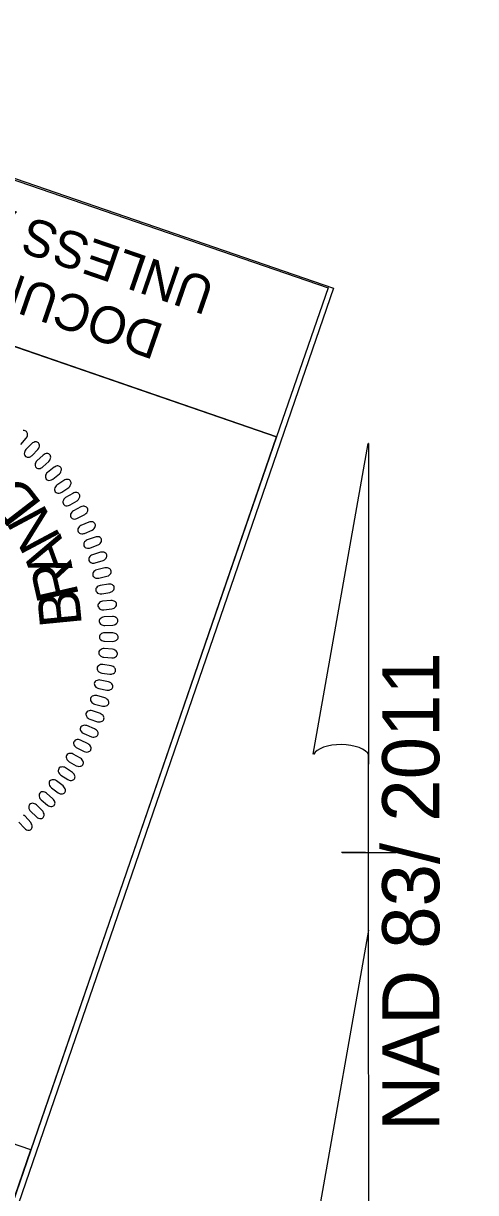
# Model space of a CAD drawing. Extents: x 479650 to 481768, y 492454 to 494037.
# Drawn here: x 479874 to 479941.4, y 492981.7 to 493156.1 of the extents above; entities that cross this region are included whole.
import ezdxf

# ---------------------------------------------------------------- set-up
doc = ezdxf.new("R2010")
doc.units = 0
for name, color, linetype in [('Prop North Arrow NAD83 for Plan Sheets CELL', 7, 'Continuous'), ('Sheet Clip Boundary CELL', 7, 'Continuous'), ('Sheet PE Seal Cell', 7, 'Continuous'), ('Sheet Plan CELL', 7, 'Continuous'), ('Sheet Sticker Exception Certification CELL', 7, 'Continuous')]:
    doc.layers.add(name, color=color, linetype=linetype)

msp = doc.modelspace()

# ---------------------------------------------------------------- linework, layer by layer
at = {"layer": 'Prop North Arrow NAD83 for Plan Sheets CELL'}
for p, q in [((479917.21, 493047.06), (479925.41, 493093.41)), ((479925.46, 493093.41), (479925.41, 493093.41)), ((479925.46, 493093.41), (479925.41, 493093.41)), ((479925.46, 493093.41), (479925.46, 493045.61)), ((479925.46, 493020.81), (479925.46, 493047.01)), ((479925.46, 493045.61), (479925.46, 493046.96)), ((479921.46, 493032.41), (479921.41, 493032.41)), ((479925.01, 493032.41), (479921.46, 493032.41)), ((479921.51, 493032.41), (479929.51, 493032.41)), ((479925.46, 493020.81), (479917.11, 492973.56)), ((479925.51, 492973.76), (479925.46, 493020.81))]:
    msp.add_line(p, q, dxfattribs=at)
msp.add_ellipse((479921.35, 493046.56), major_axis=(4.23, -0.03), ratio=0.461098, start_param=0.216388, end_param=2.908219, dxfattribs=at)
at = {"layer": 'Sheet Clip Boundary CELL'}
msp.add_lwpolyline([(480865.41, 492806.9), (480865.41, 492806.9), (481216.52, 493064.43), (481296.64, 493123.2), (481433.97, 493521.82), (480177.88, 493954.83), (480146.86, 493864.82), (480073.72, 493890.25), (479959.68, 493732.81), (479819.95, 493331.12), (479813.6, 493153.33), (479920.24, 493116.59), (479863.72, 492952.49), (480677.4, 492672.07), (480745.44, 492725.05)], close=True, dxfattribs=at)
at = {"layer": 'Sheet PE Seal Cell'}
for points in [[(479873.62, 493093.28), (479874.42, 493094.22), (479874.54, 493094.41), (479874.59, 493094.55), (479874.61, 493094.75), (479874.61, 493094.89), (479874.58, 493095.03), (479874.53, 493095.13), (479874.45, 493095.21), (479874.36, 493095.27), (479874.24, 493095.33), (479874.13, 493095.35), (479873.98, 493095.34)], [(479873.32, 493036.93), (479874.15, 493036.02), (479874.32, 493035.88), (479874.45, 493035.81), (479874.65, 493035.76), (479874.8, 493035.75), (479874.93, 493035.76), (479875.04, 493035.8), (479875.13, 493035.86), (479875.2, 493035.95), (479875.27, 493036.06), (479875.31, 493036.17), (479875.32, 493036.31), (479875.31, 493036.41), (479875.26, 493036.57), (479875.18, 493036.74), (479875.09, 493036.88), (479874.26, 493037.81), (479874.13, 493037.92), (479874, 493038)]]:
    msp.add_lwpolyline(points, dxfattribs=at)
for points in [[(479875.31, 493091.64), (479876.16, 493092.52), (479876.29, 493092.7), (479876.35, 493092.84), (479876.39, 493093.04), (479876.39, 493093.18), (479876.37, 493093.32), (479876.32, 493093.42), (479876.26, 493093.51), (479876.16, 493093.58), (479876.06, 493093.64), (479875.94, 493093.67), (479875.79, 493093.67), (479875.69, 493093.65), (479875.54, 493093.59), (479875.37, 493093.51), (479875.25, 493093.41), (479874.37, 493092.51), (479874.26, 493092.38), (479874.2, 493092.24), (479874.15, 493092.07), (479874.13, 493091.89), (479874.15, 493091.76), (479874.22, 493091.61), (479874.31, 493091.49), (479874.45, 493091.42), (479874.56, 493091.38), (479874.72, 493091.36), (479874.92, 493091.4), (479875.09, 493091.48), (479875.21, 493091.56)], [(479876.89, 493089.92), (479877.8, 493090.74), (479877.94, 493090.92), (479878.01, 493091.05), (479878.06, 493091.25), (479878.08, 493091.39), (479878.06, 493091.53), (479878.02, 493091.64), (479877.96, 493091.73), (479877.87, 493091.8), (479877.77, 493091.87), (479877.65, 493091.91), (479877.51, 493091.92), (479877.41, 493091.91), (479877.25, 493091.86), (479877.08, 493091.78), (479876.95, 493091.69), (479876.01, 493090.85), (479875.9, 493090.72), (479875.83, 493090.6), (479875.77, 493090.42), (479875.74, 493090.25), (479875.74, 493090.12), (479875.81, 493089.96), (479875.89, 493089.84), (479876.02, 493089.76), (479876.13, 493089.71), (479876.29, 493089.68), (479876.49, 493089.71), (479876.67, 493089.78), (479876.79, 493089.84)], [(479878.41, 493088.11), (479879.37, 493088.88), (479879.51, 493089.05), (479879.59, 493089.17), (479879.65, 493089.37), (479879.68, 493089.51), (479879.67, 493089.65), (479879.64, 493089.76), (479879.58, 493089.86), (479879.5, 493089.93), (479879.4, 493090.01), (479879.29, 493090.05), (479879.14, 493090.07), (479879.04, 493090.07), (479878.88, 493090.03), (479878.71, 493089.96), (479878.57, 493089.88), (479877.58, 493089.1), (479877.46, 493088.98), (479877.38, 493088.86), (479877.31, 493088.69), (479877.27, 493088.51), (479877.27, 493088.39), (479877.32, 493088.23), (479877.4, 493088.1), (479877.53, 493088), (479877.63, 493087.95), (479877.79, 493087.92), (479877.99, 493087.93), (479878.18, 493087.99), (479878.3, 493088.05)], [(479879.74, 493086.16), (479880.75, 493086.86), (479880.91, 493087.02), (479880.99, 493087.14), (479881.07, 493087.33), (479881.1, 493087.47), (479881.1, 493087.61), (479881.07, 493087.72), (479881.03, 493087.82), (479880.95, 493087.9), (479880.85, 493087.98), (479880.74, 493088.04), (479880.6, 493088.06), (479880.5, 493088.07), (479880.34, 493088.04), (479880.16, 493087.98), (479880.02, 493087.91), (479878.98, 493087.2), (479878.86, 493087.08), (479878.77, 493086.96), (479878.69, 493086.8), (479878.64, 493086.63), (479878.63, 493086.5), (479878.67, 493086.34), (479878.74, 493086.2), (479878.86, 493086.1), (479878.96, 493086.05), (479879.11, 493086), (479879.32, 493086), (479879.51, 493086.05), (479879.63, 493086.1)], [(479880.97, 493084.25), (479882.02, 493084.89), (479882.19, 493085.04), (479882.28, 493085.16), (479882.37, 493085.34), (479882.41, 493085.48), (479882.42, 493085.62), (479882.4, 493085.73), (479882.36, 493085.83), (479882.28, 493085.92), (479882.19, 493086.01), (479882.09, 493086.06), (479881.95, 493086.1), (479881.85, 493086.11), (479881.69, 493086.09), (479881.5, 493086.05), (479881.35, 493085.98), (479880.28, 493085.34), (479880.14, 493085.23), (479880.05, 493085.12), (479879.96, 493084.96), (479879.9, 493084.79), (479879.88, 493084.67), (479879.91, 493084.5), (479879.97, 493084.36), (479880.08, 493084.26), (479880.18, 493084.19), (479880.33, 493084.14), (479880.54, 493084.12), (479880.73, 493084.16), (479880.85, 493084.2)], [(479882.07, 493082.26), (479883.16, 493082.83), (479883.33, 493082.96), (479883.43, 493083.08), (479883.53, 493083.25), (479883.58, 493083.39), (479883.6, 493083.53), (479883.59, 493083.64), (479883.55, 493083.75), (479883.48, 493083.84), (479883.4, 493083.93), (479883.3, 493083.99), (479883.16, 493084.04), (479883.06, 493084.06), (479882.9, 493084.05), (479882.71, 493084.01), (479882.56, 493083.96), (479881.45, 493083.38), (479881.31, 493083.28), (479881.2, 493083.18), (479881.1, 493083.02), (479881.03, 493082.86), (479881.01, 493082.74), (479881.03, 493082.57), (479881.08, 493082.43), (479881.18, 493082.31), (479881.28, 493082.25), (479881.42, 493082.18), (479881.63, 493082.15), (479881.82, 493082.18), (479881.95, 493082.21)], [(479883.13, 493080.01), (479884.25, 493080.51), (479884.44, 493080.64), (479884.54, 493080.74), (479884.65, 493080.91), (479884.71, 493081.05), (479884.74, 493081.18), (479884.73, 493081.29), (479884.7, 493081.4), (479884.64, 493081.5), (479884.56, 493081.6), (479884.47, 493081.67), (479884.33, 493081.72), (479884.24, 493081.74), (479884.07, 493081.74), (479883.88, 493081.72), (479883.73, 493081.68), (479882.58, 493081.17), (479882.43, 493081.08), (479882.32, 493080.98), (479882.22, 493080.84), (479882.13, 493080.68), (479882.1, 493080.56), (479882.11, 493080.39), (479882.15, 493080.24), (479882.25, 493080.12), (479882.34, 493080.05), (479882.48, 493079.97), (479882.69, 493079.93), (479882.88, 493079.95), (479883.01, 493079.97)], [(479883.98, 493077.85), (479885.13, 493078.28), (479885.32, 493078.39), (479885.44, 493078.49), (479885.56, 493078.65), (479885.62, 493078.78), (479885.66, 493078.91), (479885.66, 493079.02), (479885.64, 493079.14), (479885.58, 493079.23), (479885.51, 493079.34), (479885.42, 493079.41), (479885.29, 493079.48), (479885.19, 493079.5), (479885.03, 493079.51), (479884.84, 493079.51), (479884.68, 493079.47), (479883.5, 493079.04), (479883.35, 493078.96), (479883.24, 493078.87), (479883.12, 493078.73), (479883.03, 493078.57), (479882.99, 493078.45), (479882.99, 493078.29), (479883.02, 493078.14), (479883.11, 493078.01), (479883.19, 493077.93), (479883.33, 493077.85), (479883.53, 493077.8), (479883.73, 493077.8), (479883.86, 493077.81)], [(479884.7, 493075.61), (479885.87, 493075.97), (479886.07, 493076.07), (479886.19, 493076.16), (479886.32, 493076.31), (479886.39, 493076.44), (479886.44, 493076.57), (479886.45, 493076.68), (479886.43, 493076.8), (479886.38, 493076.9), (479886.32, 493077), (479886.23, 493077.08), (479886.1, 493077.16), (479886.01, 493077.19), (479885.85, 493077.21), (479885.66, 493077.21), (479885.5, 493077.19), (479884.29, 493076.83), (479884.14, 493076.76), (479884.02, 493076.67), (479883.89, 493076.54), (479883.79, 493076.4), (479883.74, 493076.28), (479883.73, 493076.11), (479883.76, 493075.96), (479883.84, 493075.83), (479883.92, 493075.75), (479884.05, 493075.65), (479884.24, 493075.59), (479884.44, 493075.58), (479884.57, 493075.59)], [(479885.26, 493073.33), (479886.45, 493073.61), (479886.66, 493073.7), (479886.78, 493073.78), (479886.92, 493073.93), (479887.01, 493074.05), (479887.06, 493074.18), (479887.07, 493074.29), (479887.07, 493074.4), (479887.02, 493074.5), (479886.96, 493074.61), (479886.88, 493074.7), (479886.76, 493074.78), (479886.67, 493074.82), (479886.51, 493074.85), (479886.32, 493074.87), (479886.16, 493074.85), (479884.93, 493074.57), (479884.77, 493074.51), (479884.65, 493074.43), (479884.52, 493074.31), (479884.4, 493074.17), (479884.35, 493074.05), (479884.33, 493073.89), (479884.34, 493073.74), (479884.42, 493073.6), (479884.49, 493073.51), (479884.62, 493073.41), (479884.81, 493073.33), (479885, 493073.31), (479885.13, 493073.31)], [(479885.68, 493070.99), (479886.89, 493071.2), (479887.1, 493071.27), (479887.23, 493071.35), (479887.37, 493071.48), (479887.47, 493071.6), (479887.52, 493071.72), (479887.55, 493071.83), (479887.55, 493071.95), (479887.51, 493072.05), (479887.46, 493072.17), (479887.38, 493072.26), (479887.27, 493072.35), (479887.18, 493072.39), (479887.02, 493072.43), (479886.83, 493072.46), (479886.67, 493072.46), (479885.43, 493072.25), (479885.27, 493072.2), (479885.14, 493072.13), (479885, 493072.02), (479884.88, 493071.88), (479884.81, 493071.77), (479884.78, 493071.61), (479884.79, 493071.46), (479884.85, 493071.32), (479884.92, 493071.22), (479885.04, 493071.11), (479885.23, 493071.02), (479885.42, 493070.99), (479885.55, 493070.98)], [(479885.97, 493068.61), (479887.19, 493068.75), (479887.4, 493068.81), (479887.54, 493068.87), (479887.69, 493069), (479887.79, 493069.11), (479887.86, 493069.23), (479887.89, 493069.34), (479887.89, 493069.45), (479887.86, 493069.56), (479887.82, 493069.68), (479887.75, 493069.78), (479887.64, 493069.87), (479887.55, 493069.92), (479887.4, 493069.97), (479887.21, 493070.01), (479887.05, 493070.02), (479885.8, 493069.89), (479885.63, 493069.85), (479885.5, 493069.79), (479885.35, 493069.68), (479885.22, 493069.56), (479885.16, 493069.45), (479885.11, 493069.29), (479885.11, 493069.14), (479885.17, 493068.99), (479885.23, 493068.9), (479885.34, 493068.78), (479885.52, 493068.68), (479885.71, 493068.63), (479885.84, 493068.62)], [(479886.12, 493066.28), (479887.34, 493066.34), (479887.56, 493066.38), (479887.7, 493066.44), (479887.86, 493066.56), (479887.97, 493066.66), (479888.04, 493066.78), (479888.08, 493066.88), (479888.09, 493067), (479888.07, 493067.11), (479888.03, 493067.23), (479887.97, 493067.33), (479887.86, 493067.43), (479887.78, 493067.48), (479887.63, 493067.55), (479887.44, 493067.6), (479887.28, 493067.61), (479886.03, 493067.56), (479885.86, 493067.53), (479885.72, 493067.48), (479885.57, 493067.39), (479885.43, 493067.27), (479885.36, 493067.17), (479885.3, 493067.01), (479885.29, 493066.86), (479885.34, 493066.71), (479885.39, 493066.61), (479885.5, 493066.48), (479885.67, 493066.37), (479885.86, 493066.31), (479885.99, 493066.29)], [(479886.1, 493063.92), (479887.33, 493063.9), (479887.55, 493063.93), (479887.69, 493063.98), (479887.86, 493064.09), (479887.97, 493064.18), (479888.06, 493064.29), (479888.1, 493064.4), (479888.12, 493064.51), (479888.1, 493064.62), (479888.07, 493064.74), (479888.02, 493064.85), (479887.92, 493064.95), (479887.84, 493065.02), (479887.69, 493065.09), (479887.51, 493065.15), (479887.35, 493065.17), (479886.1, 493065.2), (479885.93, 493065.18), (479885.79, 493065.14), (479885.63, 493065.06), (479885.48, 493064.95), (479885.4, 493064.85), (479885.34, 493064.69), (479885.32, 493064.54), (479885.36, 493064.39), (479885.4, 493064.29), (479885.5, 493064.16), (479885.67, 493064.04), (479885.85, 493063.97), (479885.98, 493063.94)], [(479885.98, 493061.55), (479887.2, 493061.45), (479887.42, 493061.47), (479887.57, 493061.51), (479887.74, 493061.61), (479887.86, 493061.69), (479887.95, 493061.8), (479888, 493061.9), (479888.03, 493062.01), (479888.02, 493062.12), (479888, 493062.24), (479887.95, 493062.35), (479887.85, 493062.47), (479887.78, 493062.53), (479887.64, 493062.61), (479887.46, 493062.69), (479887.3, 493062.72), (479886.05, 493062.83), (479885.88, 493062.82), (479885.74, 493062.79), (479885.57, 493062.71), (479885.42, 493062.61), (479885.34, 493062.52), (479885.26, 493062.37), (479885.23, 493062.22), (479885.26, 493062.07), (479885.3, 493061.96), (479885.39, 493061.83), (479885.55, 493061.69), (479885.72, 493061.61), (479885.85, 493061.57)], [(479885.67, 493059.18), (479886.88, 493059), (479887.11, 493059.01), (479887.25, 493059.04), (479887.44, 493059.12), (479887.56, 493059.2), (479887.65, 493059.3), (479887.71, 493059.4), (479887.74, 493059.51), (479887.74, 493059.62), (479887.73, 493059.75), (479887.68, 493059.86), (479887.6, 493059.98), (479887.53, 493060.05), (479887.39, 493060.14), (479887.22, 493060.22), (479887.07, 493060.27), (479885.82, 493060.45), (479885.65, 493060.45), (479885.51, 493060.43), (479885.34, 493060.36), (479885.18, 493060.27), (479885.09, 493060.19), (479885.01, 493060.04), (479884.97, 493059.9), (479884.99, 493059.74), (479885.02, 493059.63), (479885.1, 493059.49), (479885.25, 493059.35), (479885.42, 493059.26), (479885.54, 493059.21)], [(479885.23, 493056.87), (479886.43, 493056.62), (479886.65, 493056.61), (479886.8, 493056.63), (479886.99, 493056.71), (479887.11, 493056.78), (479887.22, 493056.87), (479887.27, 493056.97), (479887.32, 493057.07), (479887.32, 493057.19), (479887.32, 493057.31), (479887.28, 493057.42), (479887.2, 493057.55), (479887.14, 493057.62), (479887.01, 493057.72), (479886.84, 493057.81), (479886.69, 493057.87), (479885.46, 493058.13), (479885.29, 493058.15), (479885.14, 493058.13), (479884.97, 493058.08), (479884.81, 493058), (479884.71, 493057.92), (479884.62, 493057.77), (479884.57, 493057.63), (479884.58, 493057.48), (479884.61, 493057.37), (479884.68, 493057.22), (479884.82, 493057.07), (479884.98, 493056.97), (479885.1, 493056.91)], [(479884.61, 493054.56), (479885.79, 493054.24), (479886.01, 493054.22), (479886.16, 493054.23), (479886.35, 493054.29), (479886.49, 493054.36), (479886.59, 493054.44), (479886.66, 493054.53), (479886.71, 493054.64), (479886.72, 493054.75), (479886.72, 493054.87), (479886.69, 493054.99), (479886.62, 493055.12), (479886.56, 493055.2), (479886.43, 493055.3), (479886.28, 493055.41), (479886.13, 493055.47), (479884.92, 493055.81), (479884.75, 493055.83), (479884.6, 493055.83), (479884.43, 493055.78), (479884.26, 493055.71), (479884.16, 493055.64), (479884.06, 493055.51), (479884, 493055.37), (479884, 493055.21), (479884.02, 493055.1), (479884.08, 493054.95), (479884.21, 493054.79), (479884.37, 493054.68), (479884.49, 493054.61)], [(479883.89, 493052.32), (479885.05, 493051.92), (479885.27, 493051.88), (479885.42, 493051.89), (479885.61, 493051.94), (479885.75, 493051.99), (479885.86, 493052.07), (479885.93, 493052.16), (479885.99, 493052.26), (479886.01, 493052.37), (479886.02, 493052.49), (479885.99, 493052.61), (479885.93, 493052.74), (479885.88, 493052.83), (479885.76, 493052.94), (479885.61, 493053.05), (479885.47, 493053.13), (479884.28, 493053.54), (479884.11, 493053.58), (479883.97, 493053.58), (479883.79, 493053.55), (479883.62, 493053.49), (479883.51, 493053.42), (479883.4, 493053.29), (479883.33, 493053.16), (479883.32, 493053), (479883.34, 493052.89), (479883.39, 493052.73), (479883.51, 493052.57), (479883.66, 493052.44), (479883.77, 493052.37)], [(479883, 493050.14), (479884.13, 493049.67), (479884.35, 493049.62), (479884.5, 493049.61), (479884.7, 493049.65), (479884.84, 493049.7), (479884.95, 493049.77), (479885.03, 493049.85), (479885.09, 493049.95), (479885.12, 493050.06), (479885.13, 493050.18), (479885.12, 493050.3), (479885.07, 493050.43), (479885.02, 493050.52), (479884.91, 493050.64), (479884.76, 493050.76), (479884.62, 493050.85), (479883.47, 493051.34), (479883.3, 493051.38), (479883.16, 493051.39), (479882.97, 493051.37), (479882.8, 493051.32), (479882.69, 493051.26), (479882.58, 493051.14), (479882.5, 493051.01), (479882.48, 493050.86), (479882.48, 493050.74), (479882.53, 493050.59), (479882.64, 493050.41), (479882.78, 493050.28), (479882.89, 493050.2)], [(479881.97, 493048.02), (479883.07, 493047.47), (479883.28, 493047.41), (479883.43, 493047.39), (479883.63, 493047.42), (479883.77, 493047.46), (479883.89, 493047.52), (479883.97, 493047.6), (479884.04, 493047.69), (479884.07, 493047.8), (479884.1, 493047.92), (479884.09, 493048.04), (479884.05, 493048.18), (479884, 493048.27), (479883.9, 493048.4), (479883.76, 493048.53), (479883.63, 493048.62), (479882.51, 493049.18), (479882.34, 493049.24), (479882.2, 493049.26), (479882.02, 493049.25), (479881.84, 493049.21), (479881.73, 493049.16), (479881.6, 493049.04), (479881.52, 493048.92), (479881.49, 493048.77), (479881.49, 493048.65), (479881.52, 493048.49), (479881.62, 493048.31), (479881.75, 493048.17), (479881.86, 493048.09)], [(479880.81, 493045.96), (479881.88, 493045.35), (479882.09, 493045.28), (479882.23, 493045.25), (479882.44, 493045.27), (479882.58, 493045.29), (479882.71, 493045.35), (479882.79, 493045.42), (479882.87, 493045.51), (479882.9, 493045.62), (479882.94, 493045.74), (479882.94, 493045.86), (479882.9, 493046), (479882.86, 493046.09), (479882.77, 493046.22), (479882.64, 493046.36), (479882.51, 493046.46), (479881.43, 493047.09), (479881.27, 493047.16), (479881.13, 493047.19), (479880.94, 493047.19), (479880.77, 493047.16), (479880.65, 493047.12), (479880.52, 493047.01), (479880.43, 493046.89), (479880.39, 493046.74), (479880.38, 493046.63), (479880.4, 493046.47), (479880.49, 493046.28), (479880.61, 493046.13), (479880.71, 493046.04)], [(479879.58, 493043.96), (479880.61, 493043.28), (479880.81, 493043.19), (479880.96, 493043.16), (479881.16, 493043.16), (479881.3, 493043.18), (479881.43, 493043.23), (479881.52, 493043.3), (479881.6, 493043.38), (479881.65, 493043.48), (479881.69, 493043.6), (479881.7, 493043.72), (479881.67, 493043.86), (479881.64, 493043.96), (479881.55, 493044.1), (479881.43, 493044.24), (479881.31, 493044.35), (479880.27, 493045.05), (479880.11, 493045.12), (479879.97, 493045.16), (479879.79, 493045.18), (479879.61, 493045.16), (479879.49, 493045.12), (479879.35, 493045.02), (479879.26, 493044.91), (479879.21, 493044.76), (479879.19, 493044.65), (479879.2, 493044.49), (479879.28, 493044.3), (479879.39, 493044.14), (479879.48, 493044.04)], [(479878.18, 493042.06), (479879.16, 493041.32), (479879.36, 493041.22), (479879.5, 493041.17), (479879.71, 493041.16), (479879.85, 493041.17), (479879.98, 493041.21), (479880.08, 493041.27), (479880.16, 493041.35), (479880.21, 493041.45), (479880.26, 493041.57), (479880.28, 493041.68), (479880.26, 493041.83), (479880.23, 493041.92), (479880.15, 493042.07), (479880.05, 493042.22), (479879.93, 493042.34), (479878.93, 493043.1), (479878.78, 493043.19), (479878.65, 493043.23), (479878.46, 493043.26), (479878.29, 493043.25), (479878.16, 493043.22), (479878.02, 493043.13), (479877.91, 493043.03), (479877.86, 493042.88), (479877.83, 493042.77), (479877.84, 493042.61), (479877.9, 493042.41), (479878, 493042.25), (479878.09, 493042.15)], [(479876.64, 493040.27), (479877.57, 493039.47), (479877.76, 493039.36), (479877.9, 493039.31), (479878.1, 493039.28), (479878.25, 493039.28), (479878.38, 493039.32), (479878.48, 493039.37), (479878.57, 493039.44), (479878.63, 493039.54), (479878.68, 493039.65), (479878.71, 493039.77), (479878.7, 493039.91), (479878.68, 493040.01), (479878.61, 493040.16), (479878.51, 493040.32), (479878.4, 493040.44), (479877.46, 493041.27), (479877.31, 493041.36), (479877.18, 493041.42), (479877, 493041.45), (479876.82, 493041.46), (479876.69, 493041.44), (479876.55, 493041.36), (479876.44, 493041.26), (479876.37, 493041.12), (479876.34, 493041.01), (479876.33, 493040.84), (479876.38, 493040.64), (479876.47, 493040.48), (479876.55, 493040.37)], [(479875.06, 493038.57), (479875.94, 493037.72), (479876.12, 493037.59), (479876.26, 493037.53), (479876.46, 493037.49), (479876.61, 493037.49), (479876.74, 493037.51), (479876.84, 493037.56), (479876.94, 493037.63), (479877, 493037.72), (479877.06, 493037.83), (479877.09, 493037.94), (479877.09, 493038.09), (479877.08, 493038.19), (479877.02, 493038.34), (479876.93, 493038.51), (479876.83, 493038.64), (479875.94, 493039.52), (479875.8, 493039.62), (479875.67, 493039.68), (479875.49, 493039.73), (479875.31, 493039.75), (479875.19, 493039.73), (479875.04, 493039.66), (479874.92, 493039.57), (479874.84, 493039.44), (479874.81, 493039.33), (479874.79, 493039.17), (479874.83, 493038.96), (479874.91, 493038.79), (479874.98, 493038.68)]]:
    msp.add_lwpolyline(points, close=True, dxfattribs=at)
at = {"layer": 'Sheet Plan CELL'}
msp.add_line((479871.05, 492976.25), (479875.11, 492988.06), dxfattribs=at)
for points in [[(481433.97, 493521.82), (481091.97, 492529.1), (479862.87, 492952.53), (479911.74, 493094.42), (479722.62, 493159.59), (480015.77, 494010.44)], [(479875.11, 492988.06), (479780.52, 493020.65), (479817.17, 493127.03), (479911.74, 493094.42)]]:
    msp.add_lwpolyline(points, close=True, dxfattribs=at)
at = {"layer": 'Sheet Sticker Exception Certification CELL'}
for p, q in [((479730.27, 493181.8), (479919.4, 493116.63)), ((479730.27, 493181.8), (479919.4, 493116.63)), ((479911.74, 493094.42), (479722.62, 493159.58)), ((479911.74, 493094.42), (479722.62, 493159.58)), ((479919.4, 493116.63), (479911.74, 493094.42)), ((479919.4, 493116.63), (479911.74, 493094.42))]:
    msp.add_line(p, q, dxfattribs=at)

# ---------------------------------------------------------------- texts
at = {"layer": 'Prop North Arrow NAD83 for Plan Sheets CELL'}
msp.add_text('NAD 83/ 2011', height=8.5, rotation=90, dxfattribs=at).set_placement((479935.98, 492990.89))
at = {"layer": 'Sheet PE Seal Cell'}
for s, rotation, p in [('D', 127.5717, (479876.91, 493084.33)), ('N', 118.082, (479879.68, 493079.37)), ('A', 109.9708, (479881.37, 493074.83)), ('R', 102.854, (479882.31, 493070.68)), ('B', 95.5789, (479882.73, 493066.35))]:
    msp.add_text(s, height=6.24, rotation=rotation, dxfattribs=at).set_placement(p)
at = {"layer": 'Sheet Sticker Exception Certification CELL'}
for s, p in [('UNLESS ALL SIGNATURES COMPLETED', (479902.85, 493117.73)), ('UNLESS ALL SIGNATURES COMPLETED', (479902.85, 493117.73)), ('DOCUMENT NOT CONSIDERED FINAL', (479895.19, 493111.06)), ('DOCUMENT NOT CONSIDERED FINAL', (479895.19, 493111.06))]:
    msp.add_text(s, height=5.5, rotation=160.9892, dxfattribs=at).set_placement(p)

doc.saveas('drawing.dxf')
